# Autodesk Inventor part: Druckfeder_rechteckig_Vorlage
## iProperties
Created: 2002-02
Part Number: Druckfeder_rechteckig_Vorlage
Material: Stahl (schweißbar)
Description: Druckfeder
Vendor: Fa. FIBRO
Document SubType Name: Modellieren
Designer: swi
Control State: 0
Master: False
Checked Out: False
Last Check In Date: 2002-05-16
Last Check In By: swi
Shininess: 20.0
Length Units: 11269
Angle Units: 11279
Time Units: 11290
Mass Units: 11283
Length Display Precision: 3
Angle Display Precision: 2
Density: 0.0
Volumn: 0.0
Area: 0.0
PropertySet Name: Model Information
Author: swi
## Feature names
1. Spirale1
2. Trennen1
3. Trennen2
